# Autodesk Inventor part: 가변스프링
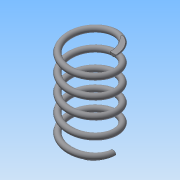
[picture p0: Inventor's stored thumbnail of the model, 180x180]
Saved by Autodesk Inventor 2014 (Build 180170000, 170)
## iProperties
Created: 2018-04
Part Number: 가변스프링
Material: 일반
Document SubType Name: Modeling
Designer: net
Density: 1 g/cm^3
Appearance: 기본값
Mass: 12.1637 g
Surface Area: 98.789 cm^2
Volume: 12.1637 cm^3
Author: net
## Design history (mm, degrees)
sketch "스케치1"
  geometry: L1 (0, 0)-(20, 0); L2 (20, 0)-(20, 75.25); L3 (20, 75.25)-(0, 75.25); L4 (0, 75.25)-(0, 0); C1 r 2.5 at (20, 0)
  constraints: 8 end point, 2 parallel, 1 centre point, 1 coincident, 1 horizontal, 1 perpendicular
  dimensions: "d0" = 40 diameter of L2 L4; "d1" = 75.25 distance between parallel lines of L1 L3 (derived); "d2" = 5 diameter of C1
feature "코일1" sketch "스케치1" pitch "d3" = 10; turns "d5" = 5; dims "d4" = 75.25 (= d1), "d6" = 0, angle "d7" = 90 deg, angle "d8" = 90 deg, "d9" = 0, "d10" = 0
node "작업 평면1"
sketch "스케치2"
  geometry: L1 (0, 2.5)-(0, -2.5) reference; L2 (0, 2.5)-(0, -2.5) reference; 1 further point
  constraints: 2 vertical alignment
extrude "돌출1" cut sketch "스케치2" distance "d11" = 10; taper "d12" = 0 deg
node "작업 평면2"
sketch "스케치3"
  geometry: L1 (0, -2.5)-(0, 2.5) reference; 1 further point
  constraints: 1 vertical alignment
extrude "돌출2" cut sketch "스케치3" distance "d13" = 10; taper "d14" = 0 deg
node "솔리드1"
node "절단 모서리 투영1"
node "절단 모서리 투영2"
node "절단 모서리 투영3"
